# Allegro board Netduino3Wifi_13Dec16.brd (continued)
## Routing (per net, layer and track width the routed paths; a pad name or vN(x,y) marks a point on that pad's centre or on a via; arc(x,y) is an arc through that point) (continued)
JTMS: length 28.8
  TOP w0.15: U4.72 48.03,30.08 49.61,28.5 52.8,28.5 53.65,27.65 v1(54.57,27.65) ; v1(60.79,36.76) 61.7,35.85 62.25,35.85 63.67,34.43 63.67,32.72 v1(63.05,32.1)
  BOTTOM w0.15: J8.2 62.9,31.18 63.05,31.33 v1(63.05,32.1) ; v1(60.79,36.76) 59.68,35.66 59.68,34.55 57.96,32.83 57.09,32.83 56.8,32.53 56.8,31.66 55.75,30.62 55.75,28.73 55.35,28.33 55.25,28.33 v1(54.57,27.65)
LED: length 31.3
  TOP w0.15: v1(43.73,22.11) 43.19,22.11 ; 43.19,22.11 42.37,22.93 R8.4 ; 43.19,22.11 43.19,21.46 43.3,21.35 43.3,19.95 42.5,19.15 42.5,18.65 42.15,18.3 41.55,18.3 40.6,19.25 40.6,20 40.45,20.15 Q1.2 ; v1(50.06,29.88) 49.68,29.88 49.53,30.03 U4.69
  BOTTOM w0.15: v1(50.06,29.88) 50.75,29.19 50.75,22.26 51,22.01 51,19.62 50.33,18.95 46.89,18.95 v1(43.73,22.11)
LED_GOPORT1: length 15.5
  TOP w0.15: v1(61.33,24.27) 61.17,24.27 61.08,24.18 U4.40 ; Q10.2 70.1,16.68 69.88,16.45 67.77,16.45 67.29,16.93 66.62,16.93 66.35,17.2 v1(65.12,17.2)
  BOTTOM w0.15: v1(61.33,24.27) 61.33,23.42 63.2,21.55 63.2,20.32 63.43,20.09 63.43,19.38 64.49,18.32 64.49,17.84 v1(65.12,17.2)
LED_GOPORT2: length 20.4
  TOP w0.15: v1(70.85,23.75) 70.32,23.75 70.1,23.53 Q11.5 ; U4.42 59.08,25.18 v1(58.85,24.95)
  L2-GND w0.15: v1(70.85,23.75) 70.27,23.17 68.87,23.17 68.25,22.55 68.25,21.42 68.45,21.21 68.46,21.21 68.75,20.92 68.75,20.37 68.59,20.21 67.69,20.21 66.38,21.52 64.82,21.52 64.12,22.22 62.53,22.22 59.8,24.95 v1(58.85,24.95)
LED_GOPORT3: length 15.1
  TOP w0.15: v1(68.25,20.71) 68.78,20.71 68.97,20.52 69.74,20.52 70.1,20.88 Q11.2 ; U4.45 59.57,26.68 59.52,26.73 v1(59.18,26.73)
  L2-GND w0.15: v1(59.18,26.73) 59.77,26.73 62,24.5 62,24.15 62.67,23.48 62.68,23.48 62.98,23.19 62.98,23.18 63.3,22.85 63.98,22.85 64.91,21.92 64.95,21.92 65.05,21.82 67.15,21.82 v1(68.25,20.71)
LINK_LED: length 15.4
  TOP w0.15: v1(49.4,39.95) 49.4,39.42 49.2,39.23 49.2,35.36 50.63,33.93 50.63,33.34 51.03,32.94 U4.66 ; v1(47.7,39.95) 46.05,39.95 45.5,40.5 45.5,41.2 45.35,41.35 Q12.2
  BOTTOM w0.15: v1(47.7,39.95) v1(49.4,39.95)
OTG_FS_DM: length 1.4
  TOP w0.18: R9.4 49.08,31.77 49.03,31.73 U4.70
OTG_FS_DP: length 1.5
  TOP w0.18: 48.43,32.35 48.43,31.82 48.53,31.72 U4.71
PWR_LED: length 14.1
  TOP w0.15: v1(49.73,16.91) 49.73,16.48 49.53,16.28 U4.7 ; R8.3 42.35,22.27 42.7,21.93 v1(42.7,20.95) 42.7,20.43 42.43,20.15 Q1.5
  BOTTOM w0.15: v1(42.7,20.95) 43.8,20.95 47.25,17.5 49.14,17.5 v1(49.73,16.91)
PWR_ON_GOPORT1: length 37.3
  TOP w0.15: Q6.5 70.1,14.3 69.8,14 69.25,14 68.75,13.5 68.75,12.85 67.9,12 67,12 66.15,12.85 66.15,14.11 63.96,16.3 63.25,16.3 62.83,15.88 60.1,15.88 57.75,18.22 57.75,18.58 56.85,19.48 56.85,19.71 55.91,20.65 53.84,20.65 53.55,20.94 53.55,21.7 54.57,22.72 54.57,23.36 54.18,23.75 52.3,23.75 51.51,24.54 50.17,24.54 49.88,24.25 47.65,24.25 46.58,23.18 U4.88
PWR_ON_GOPORT2: length 31.8
  TOP w0.15: v1(55.57,32.34) 55.53,32.3 U4.57
  TOP w0.18: Q6.2 v1(70.1,12.25)
  L2-GND w0.15: v1(55.57,32.34) 56.06,31.85 56.5,31.85 56.8,32.15 56.8,32.53 57.09,32.83 57.5,32.83 58.05,32.28 58.05,30.8 63.33,25.52 64.23,25.52 v1(65.15,24.6)
  BOTTOM w0.15: v1(70.1,12.25) 70.1,14.79 69.37,15.52 69.37,17.19 69.01,17.55 68.52,17.55 67.3,18.77 67.3,19.14 66.52,19.92 66.52,20.53 64.96,22.09 64.96,23.88 65.15,24.07 v1(65.15,24.6)
PWR_ON_GOPORT3: length 27.9
  TOP w0.15: Q10.5 v1(70.1,18.2) ; U4.59 54.53,31.81 v1(54.15,32.19)
  L2-GND w0.15: v1(54.15,32.19) 54.52,31.82 55.66,31.82 55.93,31.55 56.2,31.55 62.83,24.92 63.07,24.92 63.54,24.45 63.54,24.44 64.35,23.63 64.35,23.32 65.16,22.52 65.2,22.52 65.28,22.44 65.83,22.44 65.96,22.57 65.96,23.25 65.87,23.35 v1(65.87,23.9)
  BOTTOM w0.15: v1(70.1,18.2) 68.72,18.2 67.95,18.97 67.95,19.88 67.45,20.38 67.45,22.32 v1(65.87,23.9)
SCL: length 47.4
  TOP w0.15: U4.92 v1(45.9,21.18)
  BOTTOM w0.15: J3.10 26.75,49.2 36.06,49.2 36.61,48.65 37,48.65 38.4,47.25 38.6,47.25 42.25,43.6 42.25,40.42 43.22,39.45 44.02,39.45 44.8,38.67 44.8,35.72 44.91,35.61 44.91,35.59 48.06,32.44 48.06,23.34 v1(45.9,21.18)
SDA: length 56
  TOP w0.15: v1(46.42,20.68) 45.63,20.68 45.63,20.68 U4.93
  BOTTOM w0.15: v1(46.42,20.68) 47.85,19.25 50.21,19.25 50.7,19.74 50.7,21.88 50.45,22.13 50.45,28.78 49.56,29.67 49.56,33.46 51.2,35.11 51.2,39.7 49.1,41.8 48.05,41.8 44.85,45 44.85,45.15 42.2,47.8 40,47.8 38.8,49 36.68,49 36.18,49.5 28.99,49.5 J3.9
SPI3_MISO: length 50.1
  TOP w0.15: v1(35.37,11.62) 32.56,11.62 28.48,15.7 22.92,15.7 21.94,16.68 21.7,16.68 21.1,17.29 J9.7 ; U4.79 43.72,27.68 v1(43.4,27.35) ; v1(41.5,11.43) 40.4,12.53 40.4,13.74 39.98,14.17 39.98,15.2 40.58,15.8 v1(41.1,15.8) ; v1(44.25,10) 45.17,10.92 45.17,11.86 45.15,11.88 R5.4
  BOTTOM w0.15: v1(43.4,27.35) 43.4,25.2 40.6,22.4 40.6,16.3 v1(41.1,15.8) ; v1(44.25,10) 43.89,10 43.84,9.96 43.43,9.96 43.14,10.25 43.14,10.41 42.12,11.43 v1(41.5,11.43) 38.48,11.43 38.27,11.62 v1(35.37,11.62)
SPI3_MOSI: length 25.9
  TOP w0.15: v1(25.11,17.02) 25.5,17.41 J9.3 ; v1(42.25,25.5) 42.62,25.87 43.93,27.18 U4.80
  BOTTOM w0.15: v1(25.11,17.02) 25.11,17.08 25.31,17.28 26.13,18.1 27.37,18.1 27.57,17.9 33.22,17.9 33.27,17.95 33.73,17.95 35.23,19.45 36.38,19.45 37,20.07 37.64,20.07 39.85,22.28 39.85,22.5 42.25,24.9 v1(42.25,25.5)
SPI3_SCK: length 30.5
  TOP w0.15: U4.78 43.45,28.18 42.77,27.51 v1(42.77,26.98) ; v1(25.42,16.25) 24.35,16.25 23.3,17.31 J9.5
  BOTTOM w0.15: v1(25.42,16.25) 25.61,16.44 25.61,17.16 25.96,17.51 26.25,17.8 27.25,17.8 27.45,17.6 33.34,17.6 33.39,17.65 33.85,17.65 35.35,19.15 36.5,19.15 37.13,19.77 37.77,19.77 38.94,20.95 40,20.95 40.3,21.25 40.3,22.53 42.77,25 42.77,25.32 v1(42.77,26.98)
SPI4_MISO: length 81.6
  TOP w0.15: 80.65,37.4 78.7,37.4 78.49,37.61 v1(76.62,37.61) ; 80.65,37.4 81.75,37.4 82.9,36.25 82.9,35.45 79.64,32.19 79.64,31.23 80.15,30.73 80.15,25.9 80.65,25.4 ; 80.65,37.4 80.65,41.75 80.85,41.95 82.27,41.95 J12.8 ; U4.44 58.82,26.18 58.7,26.3 v1(58.6,26.3) ; 80.65,25.4 80.65,23.16 81.25,22.56 81.25,21.49 80.16,20.4 79.5,20.4 78.88,19.78 78.88,16.32 80.42,14.78 80.42,14.22 80.4,14.2 80.4,11.66 80.7,11.36 80.7,10.58 80.12,10.01 80.12,9.38 80.68,8.82 J10.8 ; 80.65,25.4 J11.8
  BOTTOM w0.15: v1(76.62,37.61) 76.1,37.61 75.08,38.64 66.04,38.64 65.4,38 65.4,37.4 65.8,37 66.45,37 66.6,36.85 66.6,35.91 65.61,34.92 61.77,34.92 61.48,34.63 61.48,33.63 59.4,31.55 59.4,29.01 57.4,27.01 57.4,26.59 57.69,26.3 v1(58.6,26.3)
SPI4_MOSI: length 77.2
  TOP w0.15: U4.5 48.53,14.38 47.98,13.82 47.98,11.94 47.85,11.82 47.85,10.8 49.45,9.2 60.2,9.2 60.4,9.4 69.35,9.4 70.5,10.55 73.9,10.55 74.9,9.55 76.1,9.55 ; 76.1,9.55 76.1,16.17 78.1,18.17 78.1,18.61 77.35,19.36 v1(77.35,21.95) ; 76.1,9.55 76.1,9.3 76.58,8.82 J10.7 ; J11.7 v1(76.75,25.4) ; J12.7 75.68,41.98 75,41.3 75,32.45 v1(76.6,30.85)
  BOTTOM w0.15: v1(76.6,30.85) 77.25,30.2 77.25,26.85 76.75,26.35 v1(76.75,25.4) 76.75,24.65 77.35,24.05 v1(77.35,21.95)
SPI4_SCK: length 80.2
  TOP w0.15: U4.1 46.53,16.98 47.13,17.58 47.56,17.58 48.98,19 55.7,19 56.1,18.6 56.4,18.6 56.49,18.51 56.62,18.51 56.7,18.42 59.85,15.27 61.73,15.27 65.6,11.4 74.11,11.4 74.82,10.69 v1(75.35,10.69) ; J12.9 77.58,40.71 77.02,40.15 77.02,38.72 76,37.69 76,34.45 79.85,30.6 79.85,25.78 79.92,25.7 79.92,24.11 ; v1(79.92,14.55) 79.92,11.43 v1(80.2,11.15) 80.2,10.51 79.82,10.13 79.82,9.25 80,9.08 80,7.7 79.85,7.55 J10.9 ; J11.9 78.42,24.11 79.92,24.11 ; 79.92,24.11 79.92,23.18 v1(80.75,22.35)
  BOTTOM w0.15: v1(79.92,14.55) 80.91,15.54 80.91,21.64 80.75,21.81 v1(80.75,22.35) ; v1(75.35,10.69) 75.35,10.69 75.35,10.7 79.75,10.7 v1(80.2,11.15)
STATE_LED: length 12.3
  TOP w0.15: U4.67 50.53,33.02 50.33,33.22 50.33,33.8 48.9,35.23 48.9,39.75 47.3,41.35 Q12.5
SWITCH1: length 89.8
  TOP w0.15: R12.1 65.1,18.1 63.6,16.6 63.13,16.6 62.7,16.18 60.22,16.18 58.05,18.34 58.05,18.7 57.15,19.6 57.15,19.83 55.83,21.15 v1(54.05,21.15) ; U4.58 55.03,30.08 55,30.05 55,29.5 54.98,29.48 v1(54.98,29.31) ; U4.94 43.93,20.18 43.8,20.31 43.8,21.47 44.01,21.68 U4.91 46.98,21.68 v1(48.75,23.45) 50.15,23.45 50.45,23.15 v1(54.07,23.15) ; v1(38.75,48.05) 38.1,48.7 23.9,48.7 23.2,48 21.77,48 21.52,47.75 20.42,47.75 19.55,48.62 SW1.4
  BOTTOM w0.15: v1(54.05,21.15) 54.15,21.25 54.15,22.55 54.07,22.62 v1(54.07,23.15) 54.07,28.43 54.58,28.94 54.61,28.94 v1(54.98,29.31) ; v1(38.75,48.05) 42.55,44.25 42.55,40.54 43.34,39.75 43.89,39.75 44.14,39.75 45.1,38.79 45.1,35.85 45.21,35.73 45.21,35.71 48.36,32.57 48.36,25.19 48.75,24.8 v1(48.75,23.45)
USART3_RX_GOPORT1: length 40.2
  TOP w0.15: U4.56 56.03,31.78 56.2,31.95 56.2,32.26 v1(56.3,32.35) ; J10.5 76.86,10.09 76.7,9.93 v1(76.7,9.4)
  L2-GND w0.15: v1(66.99,24.49) 65.67,25.82 63.63,25.82 58.35,31.1 58.35,32.16 58.35,32.4 57.63,33.13 56.96,33.13 56.3,32.46 v1(56.3,32.35)
  BOTTOM w0.15: v1(76.7,9.4) 75.8,9.4 73.15,12.05 73.15,12.45 71.88,13.72 71.8,13.72 70.88,14.65 70.88,14.87 70.25,15.49 70.25,17.64 70.6,17.99 70.6,18.41 70.31,18.7 68.64,18.7 68.25,19.09 68.25,20.01 67.75,20.5 67.75,23.73 v1(66.99,24.49)
USART3_TX_GOPORT1: length 58.2
  TOP w0.15: v1(65.46,22.94) 65.45,22.95 R1.7 ; U4.55 56.53,31.88 56.98,32.33 v1(57.3,32.33) ; v1(71.1,32.6) 72.35,32.6 74.2,30.75 74.2,26.43 79.28,21.35 v1(80.4,21.35) ; J10.4 82.02,11.64 80.84,11.64 80.7,11.78 80.7,14.05 80.72,14.07 80.72,15.53 80.25,16 v1(80.25,17.8)
  L2-GND w0.15: v1(71.1,32.6) 70.39,32.6 68.7,30.91 68.7,27.25 69.05,26.9 69.05,26.2 68.74,25.89 68.74,25.49 67.25,24 67.2,24 67.2,23.99 66.78,23.99 66.28,24.5 65.76,24.5 65.37,24.11 65.37,23.69 65.46,23.6 v1(65.46,22.94) 63.84,24.56 63.84,24.58 63.2,25.22 63.03,25.22 57.3,30.95 v1(57.3,32.33)
  BOTTOM w0.15: v1(80.4,21.35) 80.4,19.7 80.25,19.55 v1(80.25,17.8)
USART7_RX_GOPORT2: length 28.5
  TOP w0.15: U4.38 59.12,23.18 v1(58.81,22.87) ; v1(76.6,27.63) 76.6,27.02 76.95,26.67 J11.5
  L2-GND w0.15: v1(76.6,27.63) 76.6,26.16 73.76,23.32 72.1,23.32 71.89,23.53 71.33,23.53 70.7,22.9 70.7,21.89 68.72,19.91 67.52,19.91 66.91,19.3 64.51,19.3 63.36,20.45 62.05,20.45 59.63,22.87 v1(58.81,22.87)
USART7_TX_GOPORT2: length 58.4
  TOP w0.15: J11.4 80.85,27.94 80.55,28.24 80.55,30.75 80.14,31.16 v1(80.14,31.89) ; v1(78,31.65) 78,31.54 76.81,30.35 75.9,30.35 73.05,33.2 68.65,33.2 68.37,33.48 v1(65.15,33.48) ; v1(65.03,20.77) 65.59,21.33 65.59,22.06 65.2,22.45 R1.6 ; U4.39 59.47,23.68 v1(59,24.15)
  L2-GND w0.15: v1(65.03,20.77) 63.9,21.9 62.35,21.9 60.1,24.15 v1(59,24.15) 58.48,24.15 58.2,24.43 58.2,25.79 57.7,26.29 57.7,28.14 57.35,28.49 57.35,29.55 55.38,31.52 54.11,31.52 53.65,31.99 53.65,32.4 55.05,33.8 61.44,33.8 62.13,33.11 63.01,33.11 63.38,33.48 v1(65.15,33.48)
  BOTTOM w0.15: v1(80.14,31.89) 79.19,31.89 78.95,31.65 v1(78,31.65)
USART8_RX_GOPORT3: length 58.2
  TOP w0.15: v1(50.2,21.2) 49.83,20.83 49.53,20.83 47.38,18.68 U4.97 ; v1(50.65,37.55) 61.5,48.4 65.48,48.4 65.5,48.42 66.23,48.42 v1(66.6,48.05) ; v1(73.65,43.25) J12.5
  BOTTOM w0.15: v1(50.2,21.2) 50.2,21.73 50.15,21.77 50.15,28.66 49.26,29.55 49.26,36.16 v1(50.65,37.55) ; v1(73.65,43.25) 72.45,43.25 67.65,48.05 v1(66.6,48.05)
USART8_TX_GOPORT3: length 78.4
  TOP w0.15: v1(62.93,19.88) 62.93,20.53 64.3,21.9 R1.5 ; J12.4 80.85,44.52 80.6,44.77 80.6,47.2 v1(79.95,47.85) ; U4.98 47.31,18.18 48.25,19.12 49.48,20.35 55.5,20.35 v1(56.3,19.55) 57,18.85 57,18.55 59.97,15.57 63,15.57 63.22,15.8 v1(63.75,15.8)
  BOTTOM w0.15: v1(62.93,19.88) 62.93,18.08 63.1,17.91 63.1,17.49 63.09,17.48 63.09,16.46 v1(63.75,15.8) ; v1(79.95,47.85) 78.15,47.85 75.75,45.45 75.75,44.64 72.81,41.7 68.17,41.7 64.55,38.08 64.55,37 63.07,35.52 61.53,35.52 60.88,34.88 60.88,34.03 58.71,31.86 58.71,31.52 57.71,30.53 57.38,30.53 56.95,30.1 56.95,27.41 55.17,25.63 55.17,20.68 v1(56.3,19.55)
USB5V: length 7.9
  TOP w0.3: 13.4,23.52 13.4,23.87 13.15,24.12 11.6,24.12
  TOP w0.4: J5.1 11.6,24.12 11.6,26.9 10.6,27.9 F1.1
USB5V_F: length 58.5
  TOP w0.15: U4.68 50.03,33.68 49.02,34.7 45.13,34.7 43.45,33.02 43.45,30.89 42.24,29.67 42.24,29.27 38.78,25.82 38.19,25.82 37.57,25.2 35.25,25.2 34.85,24.8 13.33,24.8 12.5,25.63 12.5,26.78 11.45,27.83 11.45,31.23 11.32,31.35 Q3.3
  TOP w0.4: Q3.3 10.6,30.5 9.1,29 9.1,28.75 8.6,28.25 F1.2
USB_D+: length 46
  TOP w0.18: J5.3 11.46,22.82 11.59,22.7 12.9,22.7 ; 12.9,22.7 D4.1 ; 12.9,22.7 14.65,22.7 14.85,22.5 14.85,22.15 14.95,22.05 15.2,22.05 15.33,22.17 15.33,22.57 15.45,22.7 16.45,22.7 16.46,22.7 16.49,22.7 17.73,23.95 35.09,23.95 35.5,24.36 37.8,24.36 38.6,25.16 39.05,25.16 42.88,29 42.88,29.4 43.72,30.24 44.1,30.62 44.1,32.75 45.4,34.05 48.15,34.05 48.43,33.77 48.43,33.55
USB_D-: length 46
  TOP w0.18: 12.9,23.04 12.9,23.52 ; 12.9,23.04 11.9,23.04 11.46,23.47 J5.2 ; 12.9,23.04 16.35,23.04 17.59,24.28 34.95,24.28 35.36,24.7 37.66,24.7 38.46,25.5 38.91,25.5 42.55,29.14 42.55,29.54 43.59,30.57 43.77,30.76 43.77,32.89 45.26,34.38 48.75,34.38 49.08,34.05 R9.1
VCAP_1: length 1.3
  TOP w0.25: C17.1 61.53,28.68 U4.49
VCAP_2: length 2.2
  TOP w0.25: U4.73 47.53,32.22 47.3,32.45 C16.1
N61621: length 30.7
  TOP w0.3: C20.2 10.5,18.25 ; 10.5,18.25 J5.7 ; 10.5,18.25 10.5,17.85 11.1,17.25 R10.2 ; D4.2 13.4,21.74 13.7,21.44 v3(13.85,21.44)
  BOTTOM w0.254: 9.48,20.32 J5.7 ; J5.7 9.56,19.17 ; J5.7 10.5,21.47 ; J5.7 9.56,21.47 ; J5.7 10.5,19.17 ; J5.11 7.6,20.57 ; J5.11 8.25,20.52 ; J5.11 8.9,19.46 ; J5.11 8.9,20.47 ; 7.6,26.18 8.9,25.17 ; 7.6,26.18 6.95,25.12 ; 7.6,26.18 8.9,26.18 ; 7.6,26.18 7.6,25.07 ; 9.56,24.17 J5.6 ; J5.6 9.48,25.32 ; J5.6 10.5,24.17 ; J5.6 10.5,26.47 ; J5.6 9.56,26.47
N62667: length 7.6
  TOP w0.15: R4.1 45.25,37.55 45.8,38.1 45.8,39.15 45.55,39.4 U3.1 43.65,39.4 43.33,39.08 43.33,38.54 43.65,38.22 R6.2
N62753: length 10.4
  TOP w0.15: Q2.3 40.9,13.2 40.75,13.35 40.75,13.85 ; 40.75,13.85 40.72,13.85 40.27,14.29 40.27,14.71 40.87,15.3 45.45,15.3 46.35,14.4 R5.8 ; 40.75,13.85 Q2.2
N62779: length 2.9
  TOP w0.6: L1.1 41.77,44 U1.5
N62801: length 34.7
  TOP w0.15: D2.C 68.11,38.86 66.3,37.05 64.4,37.05 63.3,38.15 61.75,38.15 61.2,37.6 61.2,37.04 61.99,36.25 62.28,36.25 63.97,34.55 63.97,33.33 65.1,32.2 67.31,32.2 68,31.51 68,31.09 67.9,30.99 67.9,26.64 65.36,24.1 63.47,24.1 63.3,23.93 R1.1
N62883: length 12.9
  TOP w0.15: R11.6 35.34,13.75 35.5,13.59 35.5,12.65 34.91,12.06 32.92,12.06 27.7,17.29 J9.1
N62887: length 23.3
  TOP w0.15: J9.8 20,17.15 20.8,16.35 21.74,16.35 22.73,15.37 28.35,15.37 32.61,11.11 35.64,11.11 35.88,11.36 35.88,13.72 35.36,14.25 R11.7
N63081: length 7
  TOP w0.3: 57.03,14.3 57.08,14.25 C5.1 59.45,14.2 L2.1 59.6,13.2 60.32,13.2 C7.1 ; 57.03,14.3 U4.22 ; 57.03,14.3 56.71,14.3 56.53,14.48 U4.21
N63113: length 7.5
  TOP w0.2: Y1.2 52.03,11.68 52.25,11.9 52.25,12.85 52.03,13.07 U4.12
  TOP w0.3: C18.1 50,11.55 Y1.2
N63117: length 1.3
  TOP w0.2: U4.13 52.53,14.37 R7.2
N63121: length 6.1
  TOP w0.2: Y1.1 52.92,11.68 52.75,11.85 52.75,12.85 53.5,13.6 53.5,14.1 R7.1
  TOP w0.3: Y1.1 54.56,11.55 C19.1
N74908: length 60.5
  TOP w0.15: v1(41.1,21.31) 41.39,21.31 41.85,20.85 Q1.6 ; v1(67.4,8.8) 67.4,7.95 64.2,4.75 60.5,4.75 60.25,5 52.02,5 50.83,3.8 v1(50.3,3.8) ; v1(65.29,19.8) 65.29,20.32 66,21.03 66,23.11 65.71,23.4 65.66,23.4 65.56,23.5 R1.8
  BOTTOM w0.15: v1(50.3,3.8) 48.95,3.8 44.94,7.82 44.94,10.06 44.41,10.59 44.21,10.59 41.65,13.15 41.65,17.45 41.1,18 v1(41.1,21.31) ; v1(67.4,8.8) 67.4,9.6 66.2,10.8 66.2,13.12 66.55,13.47 66.55,17.96 65.29,19.21 v1(65.29,19.8)
N77511: length 1.8
  TOP w0.2: D1.C 16.15,19.2 R3.1
N77515: length 27.5
  TOP w0.15: Q1.3 v1(39.95,18.8)
  TOP w0.2: R3.2 17.7,18.5 17.9,18.3 v1(17.9,17.98)
  BOTTOM w0.15: v1(39.95,18.8) 39.27,19.48 37.25,19.48 36.63,18.85 35.48,18.85 33.98,17.35 33.52,17.35 33.47,17.3 27.32,17.3 27.12,17.5 26.38,17.5 26.09,17.21 25.91,17.03 25.91,16.37 25.92,16.36 25.92,16.05 25.63,15.75 24.9,15.75 24.2,16.45 24.18,16.45 23.89,16.74 23.89,16.76 23.05,17.6 18.9,17.6 18.52,17.98 v1(17.9,17.98)
N83970: length 42.8
  TOP w0.15: v1(44.1,40.71) 44.84,40.71 Q12.3 ; v1(43.15,46.05) 39.85,46.05 39.35,46.55 38.11,46.55 36.56,48.1 24.14,48.1 23.44,47.4 22.02,47.4 21.77,47.15 17.1,47.15 14.15,50.1 10.6,50.1 10.35,50.35 D9.4
  BOTTOM w0.15: v1(43.15,46.05) 43.15,42.95 44.1,42 v1(44.1,40.71)
N84209: length 46.3
  TOP w0.15: Q12.6 47.35,42 47.95,42.6 47.95,43.73 45.08,46.6 39.72,46.6 39.47,46.85 38.23,46.85 36.68,48.4 24.02,48.4 23.32,47.7 21.9,47.7 21.65,47.45 17.22,47.45 14.19,50.48 10.67,50.48 10,51.15 8.93,51.15 8.75,50.97 D9.3
N89038: length 4
  TOP w0.5: L3.1 14.18,41.15 14.2,41.16
N89104: length 39.4
  TOP w0.15: R16.3 45.25,44.25 43.95,45.55 39.93,45.55 39.23,46.25 37.98,46.25 36.43,47.8 24.27,47.8 23.57,47.1 22.14,47.1 21.89,46.85 11.05,46.85 9.45,48.45 D9.2
N89108: length 40.6
  TOP w0.15: R16.4 44.73,43.17 44.35,43.55 44.35,44.5 43.6,45.25 39.8,45.25 39.1,45.95 37.86,45.95 36.31,47.5 24.39,47.5 23.69,46.8 22.27,46.8 22.02,46.55 10.65,46.55 8.75,48.45 D9.1
N89134: length 10.2
  TOP w0.18: U5.21 23.52,45.66 23.7,45.85 31.85,45.85 32.15,45.55 R18.1
N197515: length 10.6
  TOP w0.15: Q10.6 69,18.95 68.83,19.12 v1(68.83,19.4) ; R15.8 66.5,24.28 66.45,24.33 66.45,24.66 66.78,24.99 67.86,24.99 68.13,24.72 v1(68.69,24.72)
  BOTTOM w0.15: v1(68.69,24.72) 68.25,24.28 68.25,21.42 68.54,21.12 68.63,21.12 68.83,20.92 v1(68.83,19.4)
N197535: length 29.7
  TOP w0.15: R15.1 66.5,20.6 v1(65.97,20.07)
  TOP w0.18: v1(77.8,2.55) D5.C
  BOTTOM w0.15: v1(65.97,20.07) 65.97,19.35 67.59,17.74 67.59,15.86 68.8,14.65 68.8,5.99 71.14,3.65 76.7,3.65 v1(77.8,2.55)
N197921: length 6.4
  TOP w0.15: v1(69.1,23.67) 68.62,24.15 68.54,24.15 68.39,24.3 67.5,24.3 67.05,23.85 R15.7 ; v1(70.2,22.1) 70.7,21.6 70.7,21.1 Q11.3
  BOTTOM w0.15: v1(70.2,22.1) 69.47,22.83 69.47,23.3 v1(69.1,23.67)
N197949: length 16.3
  TOP w0.15: D6.C 79.45,19.05 v1(79.45,17.85) ; R15.2 67.05,21.16 68,20.21 69.85,20.21 70.02,20.38 70.17,20.52 70.91,20.52 71.06,20.38 74.28,20.38 74.75,19.9 76.1,19.9 v1(77.6,18.4)
  BOTTOM w0.15: v1(77.6,18.4) 78.9,18.4 v1(79.45,17.85)
N198166: length 3.2
  TOP w0.15: R15.6 67.55,23.85 67.7,24 68.27,24 68.5,23.77 68.5,23.3 68.85,22.95 Q11.6
N198194: length 25.4
  TOP w0.15: v1(68.75,21.62) 68.38,21.25 67.75,21.25 67.55,21.45 R15.3
  TOP w0.18: D7.C 78.84,35.75 78.49,35.4 v1(76.55,35.4)
  BOTTOM w0.15: v1(68.75,21.62) 68.75,22.15 68.55,22.35 68.55,24 68.77,24.22 69.35,24.22 69.57,24 70.39,24 70.64,24.25 71.06,24.25 71.31,24 72.95,24 73.8,24.85 73.8,32.65 v1(76.55,35.4)
N199051: length 52.7
  TOP w0.15: v1(62.48,22.98) 62.75,22.98 62.78,22.95 R1.2 ; Q4.3 35.7,16.05 36.2,15.55 36.2,14.28 36.5,13.98 36.5,10.78 36.83,10.45 36.95,10.32 40.82,10.32 43.5,7.65 60.6,7.65 61.5,8.55 v1(64.4,8.55)
  BOTTOM w0.15: v1(64.4,8.55) 64.4,14.1 65.65,15.35 65.65,17.58 63.73,19.5 63.73,20.21 63.5,20.45 63.5,21.96 v1(62.48,22.98)
N202411: length 11.6
  TOP w0.15: v1(62.74,24.12) 62.13,23.51 62.13,23.35 61.98,23.19 61.98,22.78 62.13,22.62 62.3,22.45 R1.3 ; v1(65.05,27.05) 65,27.05 64.65,27.4 64.65,29.37 64.94,29.66 65.11,29.66 Q8.6
  BOTTOM w0.15: v1(65.05,27.05) 64.35,26.35 64.35,24.67 63.8,24.12 v1(62.74,24.12)
N203046: length 11.3
  TOP w0.15: R1.4 62.39,21.9 61.68,22.62 61.68,23.31 61.83,23.47 61.83,24.13 62.05,24.35 62.05,24.35 62.95,25.25 65.28,25.25 67.05,27.02 Q8.3

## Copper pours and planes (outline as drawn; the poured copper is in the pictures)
+3.3V on TOP: 38.55,42.35 38.55,39.6 41.15,39.6 41.45,39.9 41.45,40.2 42.45,41.2 43.5,41.2 43.5,42.25 40.05,42.25 39.95,42.35
+3.3V on L3-PWR: 71.35,26 71.35,31.35 54.15,48.55 54.15,52.75 21.8,52.75 21.8,44.15 13.85,36.2 11.2,36.2 11.2,34.9 12.85,33.25 12.85,29.6 13.05,29.4 14.1,29.4 20.5,23 27.2,23 29.8,25.6 29.8,40.8 33.3,44.3 33.3,44.45 34.85,46 36.3,46 39.9,42.4 39.9,40.3 40.65,39.55 48.55,39.55 49.05,39.05 49.05,36.35 47.65,34.95 45.3,34.95 44.55,35.7 44.3,35.7 44.1,35.5 44.1,32.55 45.5,31.15 45.5,29.2 33.05,16.75 33.05,15.4 35.9,12.55 35.9,9.3 36.25,8.95 57.9,8.95 61.45,12.5 71.7,12.5 72.1,12.9 72.1,13.2 71.3,14 69.35,14 67.55,15.8 67.55,17.45 68.85,18.75 69.35,18.75 70.6,17.5 72.35,17.5 73.85,19 73.85,23.5 ; 7 cut-outs
+5.0V on TOP: 9.05,30 6.95,30 6.95,32.6 7.85,32.6 7.85,30.8 9.05,30.8
+5.0V on TOP: 33.3,46.1 33.3,43.75 33.65,43.75 33.65,42.95 35.2,42.95 35.2,43.75 36.95,43.75 36.95,46.1
+5.0V on TOP, L2-GND: 31.5,38.35 31.5,30.4 39.1,30.4 39.1,38.35
+5.0V on BOTTOM: 6.85,0.5 6.85,32.6 12.05,32.6 12.65,32 13.7,32 14,32.3 14,44.95 14.7,45.65 14.7,46.15 14,46.85 14,52.75 20.75,52.75 20.75,51.65 21.6,50.8 25.15,50.8 26.75,49.2 36.65,49.2 41.95,43.9 41.95,28.55 39.95,28.55 39.9,28.6 35.95,28.6 35.95,26.4 38.92,23.42 35.5,20 35.1,20 35.1,0.5 ; 2 cut-outs
+5.0V on L3-PWR: 6.85,32.55 6.85,0.5 82.6,0.5 83.85,1.75 83.85,51.5 82.6,52.75 6.4,52.75 0.5,46.85 0.5,38.9 ; 5 cut-outs
GND on TOP: 37.25,44.1 38.25,44.1 38.25,41.75 37.7,41.2 37.7,39.8 33.7,39.8 33.7,40.85 35.55,40.85 35.55,41.45 35.6,41.5 37.25,41.5 37.25,42.8 35.85,42.8 35.85,43.25 35.9,43.3 37.25,43.3
GND on TOP: 6.85,0.5 6.85,32.55 0.5,38.9 0.5,39.9 1,39.9 1,43.1 2.2,43.1 2.2,41.4 6.8,41.4 6.8,40.9 2.2,40.9 2.2,39.9 6.8,39.9 6.8,40.45 14.85,40.45 14.85,41.85 6.8,41.85 6.8,45.8 2.2,45.8 2.2,45.3 1,45.3 1,45.8 0.5,45.8 0.5,46.85 6.4,52.75 82.6,52.75 83.85,51.5 83.85,1.75 82.6,0.5 ; 38 cut-outs
GND on BOTTOM: 6.85,32.55 6.85,0.5 82.6,0.5 83.85,1.75 83.85,51.5 82.6,52.75 6.4,52.75 0.5,46.85 0.5,38.9 ; 32 cut-outs
GND on L2-GND: 6.85,32.55 6.85,0.5 82.6,0.5 83.85,1.75 83.85,51.5 82.6,52.75 6.4,52.75 0.5,46.85 0.5,38.9 ; 2 cut-outs
GND on L3-PWR: 21.6,52.75 21.6,44.25 13.75,36.4 8.95,36.4 8.6,36.05 8.6,32.85 6.55,32.85 0.5,38.9 0.5,46.85 6.4,52.75
N61621 on BOTTOM: 6.85,27.25 6.85,18.5 11.35,18.5 11.35,22 13.1,22 13.35,21.75 13.35,21 14.35,21 14.35,21.75 11.85,24.25 11.35,24.25 11.35,27.25

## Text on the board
Ref Des/Silkscreen Top: 7.5-12V | ACT | MicroSD | REV.A | PWR | Power | Digital I/O | Analog In | LED | SC | SD | GND | 13 | IOREF | 12 | /RESET | 11 | 3V3 | 10 | 5V | 9 | 8 | 7 | VIN | 6 | 5 | 0 | 4 | 1 | 3 | 2
User.8: FIGURE | SIZE | 0.25 | 0.3302 | 0.5 | 0.8 | 1.0 | 1.8 | 2.4 | 3.2 | 1.0x0.75 | 1.3x0.75 | DRILL CHART: TOP to BOTTOM | ALL UNITS ARE IN MILLIMETERS | TOLERANCE | +0.08/-0.08 | +0.1/-0.0 | PLATED | NON-PLATED | QTY | 553 | 68 | 21 | 32 | 6 | 3 | 1 | 2
